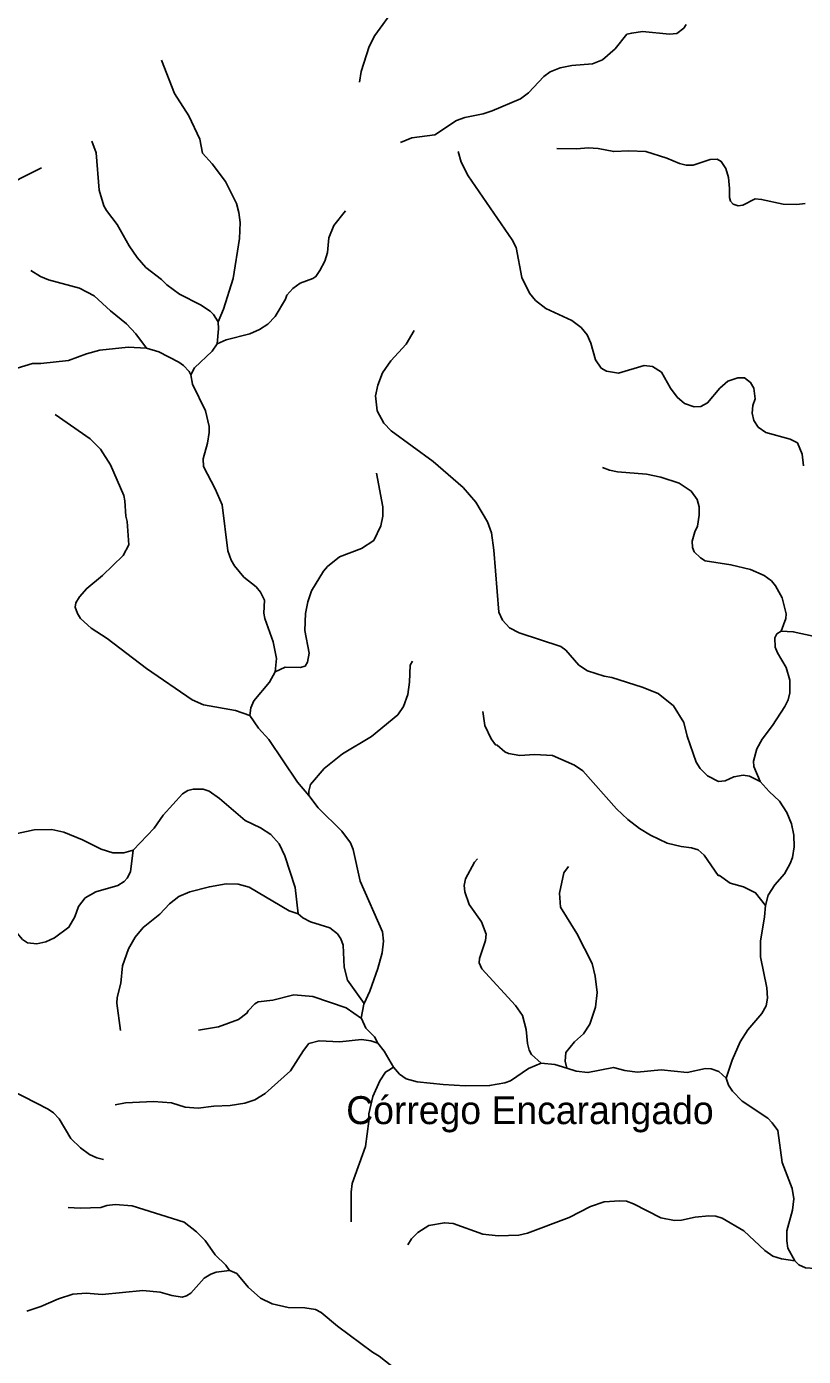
# Model space of a CAD drawing. Extents: x 500 to 555.2, y 9115.7 to 9171.
# Drawn here: x 533.92 to 538.37, y 9135.74 to 9143.36 of the extents above; entities that cross this region are included whole.
import ezdxf
from ezdxf.enums import TextEntityAlignment as Align

# ---------------------------------------------------------------- set-up
doc = ezdxf.new("R2010")
doc.units = 0
doc.header["$LTSCALE"] = 0.064
doc.layers.add('61', color=7, linetype='Continuous')
doc.layers.add('7', color=7, linetype='Continuous', lineweight=25)

msp = doc.modelspace()

# ---------------------------------------------------------------- linework, layer by layer
at = {"layer": '7'}
for points in [[(535.8279, 9143.0382), (535.8385, 9143.0985), (535.8846, 9143.2428), (535.9174, 9143.3044), (536.0326, 9143.4657), (536.1747, 9143.6424), (536.2135, 9143.6797), (536.3104, 9143.7912), (536.3603, 9143.858), (536.4244, 9143.9718), (536.4469, 9144.0394), (536.4599, 9144.1084), (536.4567, 9144.2225), (536.3979, 9144.4686), (536.3929, 9144.563)], [(536.0645, 9142.6919), (536.1293, 9142.719), (536.2598, 9142.7371), (536.3851, 9142.8175), (536.4328, 9142.8351), (536.5381, 9142.8573), (536.5886, 9142.8733), (536.7507, 9142.943), (536.7963, 9142.9767), (536.8854, 9143.0704), (536.9215, 9143.0964), (536.9786, 9143.1202), (537.0447, 9143.1324), (537.164, 9143.1435), (537.2214, 9143.1661), (537.2946, 9143.2288), (537.3612, 9143.3128), (537.3885, 9143.3191), (537.4502, 9143.3275), (537.6059, 9143.3129), (537.6469, 9143.3161), (537.6865, 9143.3469), (537.6996, 9143.3674)], [(534.6945, 9143.164), (534.769, 9142.9733), (534.8515, 9142.8457), (534.9146, 9142.7113), (534.9297, 9142.6322), (534.9848, 9142.5701), (535.0606, 9142.4685), (535.1234, 9142.3429), (535.1379, 9142.2924), (535.1445, 9142.2352), (535.1412, 9142.1432), (535.1051, 9141.9136), (535.0498, 9141.7378), (535.0187, 9141.6649)], [(534.2955, 9142.6996), (534.3198, 9142.6332), (534.3375, 9142.4194), (534.3641, 9142.3304), (534.3789, 9142.3036), (534.4408, 9142.2235), (534.5094, 9142.1007), (534.5546, 9142.0333), (534.6052, 9141.9772), (534.6951, 9141.9086), (534.7252, 9141.8771), (534.798, 9141.8239), (534.9171, 9141.7623), (534.9731, 9141.7269), (534.9924, 9141.7079), (535.0187, 9141.6649)], [(536.3937, 9142.6402), (536.412, 9142.5806), (536.4523, 9142.502), (536.704, 9142.1343), (536.7256, 9142.0907), (536.7591, 9141.9189), (536.8026, 9141.8295), (536.8379, 9141.7869), (536.8964, 9141.7414), (537.0446, 9141.6737), (537.0997, 9141.6331), (537.1331, 9141.5908), (537.155, 9141.5429), (537.1818, 9141.4478), (537.2142, 9141.4007), (537.2445, 9141.3823), (537.3124, 9141.3723), (537.4593, 9141.4162), (537.5071, 9141.4097), (537.5585, 9141.3775), (537.6111, 9141.2852), (537.6497, 9141.234), (537.6903, 9141.1986), (537.7466, 9141.1788), (537.7854, 9141.1805), (537.8228, 9141.2015), (537.8941, 9141.2858), (537.9402, 9141.3265), (537.9966, 9141.3449), (538.0346, 9141.3458), (538.07, 9141.3187), (538.0873, 9141.2863), (538.0954, 9141.2243), (538.0825, 9141.1868), (538.0778, 9141.1423), (538.0873, 9141.1002), (538.1131, 9141.0626), (538.1567, 9141.0325), (538.2959, 9140.9937), (538.3379, 9140.9719), (538.3658, 9140.907), (538.3726, 9140.8415)], [(536.9602, 9142.6582), (537.0748, 9142.6567), (537.1397, 9142.6615), (537.1971, 9142.6579), (537.2855, 9142.6403), (537.3714, 9142.6452), (537.47, 9142.6418), (537.5892, 9142.6022), (537.6622, 9142.5718), (537.7001, 9142.5632), (537.7407, 9142.5635), (537.838, 9142.5959), (537.8787, 9142.5974), (537.9014, 9142.5844), (537.9282, 9142.5428), (537.9429, 9142.493), (537.9494, 9142.4286), (537.9479, 9142.3768), (537.9546, 9142.3557), (537.9703, 9142.3388), (537.9986, 9142.3303), (538.0258, 9142.3344), (538.0968, 9142.3695), (538.1331, 9142.3662), (538.2565, 9142.3386), (538.3345, 9142.3368), (538.3831, 9142.3435)], [(534.0073, 9142.547), (533.8838, 9142.4855), (533.6785, 9142.3649), (533.6038, 9142.3354), (533.5134, 9142.3284), (533.287, 9142.2811), (533.2063, 9142.2924), (533.1083, 9142.3399)], [(535.7481, 9142.3006), (535.681, 9142.2171), (535.6531, 9142.1465), (535.6448, 9142.0618), (535.6301, 9142.0126), (535.6019, 9141.959), (535.5795, 9141.9252), (535.561, 9141.9137), (535.4885, 9141.887), (535.4477, 9141.8559), (535.4126, 9141.8191), (535.4055, 9141.7961), (535.3463, 9141.6955), (535.3027, 9141.6521), (535.2556, 9141.6214), (535.2003, 9141.5977), (535.0646, 9141.5626), (535.0126, 9141.5396)], [(533.9457, 9141.9594), (534.0008, 9141.9254), (534.0477, 9141.9059), (534.2238, 9141.8579), (534.308, 9141.815), (534.4018, 9141.7278), (534.4943, 9141.6535), (534.5471, 9141.5975), (534.6085, 9141.5154)], [(535.0187, 9141.6649), (535.0204, 9141.6247), (535.0126, 9141.5396)], [(536.1426, 9141.6157), (536.0953, 9141.5378), (536.009, 9141.4428), (535.9602, 9141.3733), (535.9337, 9141.3039), (535.9205, 9141.2411), (535.9304, 9141.1568), (535.9688, 9141.0857), (536.011, 9141.0406), (536.2512, 9140.8658), (536.4235, 9140.7165), (536.4945, 9140.6325), (536.5631, 9140.5199), (536.5846, 9140.4576), (536.5979, 9140.358), (536.6276, 9140.0038), (536.6488, 9139.9567), (536.6885, 9139.9138), (536.7442, 9139.884), (536.9816, 9139.8072), (537.0114, 9139.7856), (537.0853, 9139.7005), (537.1348, 9139.6678), (537.2307, 9139.6365), (537.2749, 9139.6298), (537.4475, 9139.5744), (537.5392, 9139.5383), (537.6279, 9139.4662), (537.6868, 9139.3711), (537.7065, 9139.293), (537.7578, 9139.1443), (537.7801, 9139.1084), (537.8226, 9139.066), (537.8861, 9139.0333), (537.9238, 9139.0383), (537.9741, 9139.061), (538.0276, 9139.0692), (538.0642, 9139.0644), (538.125, 9139.0346)], [(535.0126, 9141.5396), (534.9844, 9141.4976), (534.8834, 9141.403), (534.8618, 9141.362)], [(533.6627, 9141.1679), (533.6658, 9141.2013), (533.7145, 9141.2983), (533.7569, 9141.3475), (533.8242, 9141.3869), (533.9543, 9141.4264), (534.0029, 9141.4265), (534.1613, 9141.4446), (534.2637, 9141.4821), (534.3414, 9141.5035), (534.5043, 9141.5199), (534.6085, 9141.5154)], [(534.6085, 9141.5154), (534.6797, 9141.493), (534.7935, 9141.4346), (534.8211, 9141.415), (534.8521, 9141.381), (534.8618, 9141.362)], [(534.8618, 9141.362), (534.8719, 9141.3091), (534.9457, 9141.1564), (534.9667, 9141.0666), (534.9673, 9141.0311), (534.958, 9140.9714), (534.9332, 9140.8817), (534.9346, 9140.8372), (535.0022, 9140.7088), (535.0413, 9140.6171), (535.0738, 9140.3547), (535.0935, 9140.3002), (535.1122, 9140.2678), (535.1664, 9140.204), (535.2359, 9140.1475), (535.2622, 9140.1181), (535.2852, 9140.0713), (535.2809, 9139.9977), (535.2869, 9139.9664), (535.3333, 9139.8331), (535.3539, 9139.7381), (535.3463, 9139.6612)], [(534.0843, 9141.1347), (534.285, 9140.9952), (534.3457, 9140.9361), (534.4021, 9140.8478), (534.4779, 9140.6716), (534.4852, 9140.6401), (534.49, 9140.5528), (534.4982, 9140.5219), (534.5071, 9140.3888), (534.4749, 9140.3271), (534.3572, 9140.2139), (534.2658, 9140.1392), (534.2247, 9140.0917), (534.2032, 9140.0568), (534.1999, 9140.0328), (534.2126, 9139.9951), (534.23, 9139.9663), (534.2911, 9139.9112), (534.3834, 9139.8517), (534.6087, 9139.6807), (534.8696, 9139.502), (534.9353, 9139.4727), (535.1191, 9139.4406), (535.1998, 9139.412)], [(535.9263, 9140.799), (535.9631, 9140.6056), (535.9621, 9140.5529), (535.9518, 9140.4977), (535.9105, 9140.4144), (535.8401, 9140.3686), (535.7138, 9140.3192), (535.6454, 9140.2639), (535.6235, 9140.2372), (535.5544, 9140.1251), (535.5324, 9140.0627), (535.5188, 9139.9959), (535.5153, 9139.8987), (535.5396, 9139.7688), (535.5316, 9139.7179), (535.5169, 9139.6944), (535.4884, 9139.6861), (535.4032, 9139.689), (535.3463, 9139.6612)], [(537.2212, 9140.8311), (537.2606, 9140.8163), (537.3077, 9140.8068), (537.4737, 9140.7932), (537.5563, 9140.7766), (537.6602, 9140.7427), (537.7295, 9140.6964), (537.764, 9140.6474), (537.7755, 9140.6073), (537.7755, 9140.5582), (537.7661, 9140.4951), (537.751, 9140.4635), (537.7358, 9140.4107), (537.7364, 9140.3739), (537.7472, 9140.348), (537.7829, 9140.3134), (537.809, 9140.2968), (537.9566, 9140.2747), (538.07, 9140.2467), (538.148, 9140.2126), (538.1885, 9140.1818), (538.2132, 9140.1539), (538.2512, 9140.0845), (538.2741, 9139.9944), (538.2711, 9139.9664), (538.2453, 9139.8939)], [(538.2453, 9139.8939), (538.2204, 9139.8785), (538.2089, 9139.8572), (538.2108, 9139.8028), (538.2237, 9139.7707), (538.2727, 9139.6855), (538.2953, 9139.6146), (538.2938, 9139.5417), (538.2854, 9139.5017), (538.266, 9139.4631), (538.1954, 9139.3548), (538.1353, 9139.2767), (538.1056, 9139.2209), (538.0861, 9139.1509), (538.0881, 9139.1196), (538.125, 9139.0346)], [(538.4278, 9139.8649), (538.3136, 9139.891), (538.2453, 9139.8939)], [(536.1317, 9139.7222), (536.1199, 9139.6989), (536.1157, 9139.6015), (536.1057, 9139.532), (536.0813, 9139.4636), (536.048, 9139.4154), (535.898, 9139.2918), (535.7323, 9139.1927), (535.6264, 9139.1083), (535.5486, 9139.0172), (535.5383, 9138.9784), (535.5386, 9138.9532)], [(535.3463, 9139.6612), (535.3127, 9139.6015), (535.2237, 9139.496), (535.2065, 9139.4553), (535.1998, 9139.412)], [(535.1998, 9139.412), (535.2501, 9139.3395), (535.3098, 9139.2733), (535.474, 9139.0293), (535.5386, 9138.9532)], [(536.5359, 9139.4345), (536.5472, 9139.3542), (536.5824, 9139.2773), (536.6075, 9139.2437), (536.6173, 9139.2413), (536.6623, 9139.203), (536.6831, 9139.1942), (536.7475, 9139.1826), (536.832, 9139.1889), (536.9353, 9139.1825), (537.0598, 9139.127), (537.1087, 9139.0948), (537.302, 9138.877), (537.3666, 9138.8163), (537.4327, 9138.7654), (537.4962, 9138.7259), (537.5913, 9138.6809), (537.6719, 9138.6607), (537.7302, 9138.6542), (537.7684, 9138.6422), (537.8042, 9138.6123), (537.8832, 9138.4961), (537.8919, 9138.4949), (537.9517, 9138.4516), (538.0282, 9138.4312), (538.0979, 9138.3967), (538.1543, 9138.3243)], [(538.125, 9139.0346), (538.1763, 9138.9761), (538.2348, 9138.9216), (538.2771, 9138.8567), (538.3037, 9138.7905), (538.3183, 9138.7255), (538.3201, 9138.6592), (538.3105, 9138.5984), (538.2968, 9138.5633), (538.2631, 9138.5057), (538.2086, 9138.4427), (538.1705, 9138.3837), (538.1543, 9138.3243)], [(534.5321, 9138.6401), (534.652, 9138.7667), (534.7038, 9138.8401), (534.8141, 9138.9626), (534.8461, 9138.9823), (534.8756, 9138.9889), (534.9331, 9138.989), (534.9673, 9138.979), (535.0268, 9138.9358), (535.1746, 9138.8098), (535.262, 9138.7678), (535.3211, 9138.73), (535.3676, 9138.6773), (535.4015, 9138.6082), (535.4611, 9138.4263), (535.4774, 9138.2769)], [(535.5386, 9138.9532), (535.5924, 9138.8823), (535.7284, 9138.7494), (535.7772, 9138.6827), (535.7934, 9138.6443), (535.8333, 9138.4631), (535.9609, 9138.1731), (535.9662, 9138.1186), (535.9583, 9138.053), (535.9335, 9137.9638), (535.8876, 9137.8325), (535.8553, 9137.7623)], [(533.7538, 9138.7445), (533.7944, 9138.7326), (533.8511, 9138.7326), (533.9642, 9138.7561), (534.0667, 9138.7585), (534.1341, 9138.7445), (534.2418, 9138.7005), (534.348, 9138.6459), (534.4158, 9138.6247), (534.478, 9138.6249), (534.5321, 9138.6401)], [(533.6766, 9138.2922), (533.7562, 9138.2674), (533.7923, 9138.2445), (533.8332, 9138.2055), (533.8985, 9138.1289), (533.9262, 9138.1103), (533.9799, 9138.1033), (534.032, 9138.1157), (534.0805, 9138.1385), (534.1641, 9138.1987), (534.1976, 9138.2594), (534.2179, 9138.318), (534.2569, 9138.3667), (534.3184, 9138.4017), (534.4437, 9138.4384), (534.4803, 9138.4608), (534.4969, 9138.4794), (534.5162, 9138.5166), (534.5321, 9138.6401)], [(536.5052, 9138.591), (536.4873, 9138.5716), (536.4366, 9138.4771), (536.429, 9138.4388), (536.4325, 9138.4022), (536.4563, 9138.3292), (536.5271, 9138.2309), (536.5548, 9138.1586), (536.5506, 9138.1242), (536.5159, 9138.0195), (536.5146, 9137.9947), (536.5302, 9137.9602), (536.722, 9137.751), (536.7625, 9137.6931), (536.7846, 9137.6133), (536.7915, 9137.5327), (536.8008, 9137.4959), (536.8142, 9137.4706), (536.87, 9137.4218)], [(537.0254, 9138.5474), (537, 9138.5106), (536.9753, 9138.3947), (536.9803, 9138.314), (537.075, 9138.1639), (537.1622, 9137.991), (537.1799, 9137.9184), (537.1901, 9137.8251), (537.1818, 9137.7414), (537.1483, 9137.6441), (537.1124, 9137.5894), (537.06, 9137.5434), (537.0114, 9137.4829), (537.0079, 9137.4323), (537.016, 9137.3921)], [(534.4592, 9137.6084), (534.4393, 9137.7636), (534.4409, 9137.7964), (534.4621, 9137.8791), (534.4707, 9137.9781), (534.5046, 9138.0748), (534.5427, 9138.1425), (534.5902, 9138.1983), (534.6843, 9138.2747), (534.7394, 9138.3328), (534.7928, 9138.3761), (534.8559, 9138.4017), (534.9687, 9138.4315), (535.0653, 9138.4476), (535.1329, 9138.4457), (535.197, 9138.4279), (535.4262, 9138.2922), (535.4774, 9138.2769)], [(535.4774, 9138.2769), (535.5042, 9138.2527), (535.5474, 9138.2299), (535.6596, 9138.1949), (535.7022, 9138.162), (535.7212, 9138.1326), (535.7348, 9138.0966), (535.7415, 9137.971), (535.7606, 9137.8957), (535.8553, 9137.7623)], [(538.1543, 9138.3243), (538.1497, 9138.2585), (538.1266, 9138.1186), (538.1266, 9138.0301), (538.1626, 9137.8516), (538.1658, 9137.7926), (538.1596, 9137.75), (538.1334, 9137.7052), (538.0545, 9137.6111), (538.0094, 9137.5425), (537.9642, 9137.4387), (537.9297, 9137.3344)], [(534.9062, 9137.61), (535.0205, 9137.6293), (535.1347, 9137.6702), (535.184, 9137.7069), (535.1909, 9137.7214), (535.2282, 9137.7602), (535.249, 9137.7715), (535.332, 9137.7824), (535.4529, 9137.8128), (535.5606, 9137.8031), (535.7529, 9137.7381), (535.8398, 9137.6768)], [(535.8553, 9137.7623), (535.8538, 9137.7591), (535.8393, 9137.6779), (535.8398, 9137.6768)], [(535.8398, 9137.6768), (535.8644, 9137.6215), (535.9156, 9137.572), (535.9343, 9137.536)], [(534.4294, 9137.1817), (534.489, 9137.1944), (534.6486, 9137.201), (534.7525, 9137.1943), (534.8296, 9137.1699), (534.9042, 9137.1634), (534.9936, 9137.1748), (535.0887, 9137.1787), (535.1715, 9137.1914), (535.2285, 9137.2119), (535.2876, 9137.2477), (535.4331, 9137.3766), (535.5083, 9137.4941), (535.539, 9137.5326), (535.5973, 9137.5488), (535.716, 9137.5439), (535.8394, 9137.5568), (535.8938, 9137.5494), (535.9343, 9137.536)], [(535.9343, 9137.536), (535.9704, 9137.489), (536.0231, 9137.3973)], [(536.0231, 9137.3973), (536.0573, 9137.3582), (536.0968, 9137.3319), (536.1597, 9137.3139), (536.3085, 9137.2979), (536.4337, 9137.2912), (536.5743, 9137.2929), (536.662, 9137.3089), (536.6939, 9137.3199), (536.7966, 9137.3905), (536.87, 9137.4218)], [(536.87, 9137.4218), (536.9488, 9137.4142), (537.016, 9137.3921)], [(535.7811, 9136.5131), (535.781, 9136.6823), (535.7863, 9136.7315), (535.8629, 9136.9436), (535.8825, 9137.0879), (535.8831, 9137.1305), (535.9059, 9137.2294), (535.945, 9137.3191), (535.9786, 9137.3703), (535.9966, 9137.3815), (536.0231, 9137.3973)], [(537.016, 9137.3921), (537.0701, 9137.3743), (537.1379, 9137.3669), (537.2849, 9137.3963), (537.3498, 9137.3797), (537.4206, 9137.37), (537.558, 9137.3832), (537.7061, 9137.3668), (537.811, 9137.3895), (537.8444, 9137.3879), (537.8885, 9137.3723), (537.9297, 9137.3344)], [(537.9297, 9137.3344), (537.9423, 9137.2957), (537.9652, 9137.2606), (538.0205, 9137.2024), (538.168, 9137.1052), (538.1938, 9137.0796), (538.2249, 9137.0352), (538.2497, 9136.8517), (538.307, 9136.704), (538.3168, 9136.645), (538.3102, 9136.5795)], [(534.3621, 9136.8685), (534.3233, 9136.8783), (534.2819, 9136.8975), (534.2299, 9136.9362), (534.1748, 9136.9888), (534.1084, 9137.1018), (534.0755, 9137.1367), (534.0455, 9137.1583), (533.8321, 9137.2661)], [(534.1603, 9136.5949), (534.2278, 9136.591), (534.3473, 9136.5942), (534.3808, 9136.6056), (534.4294, 9136.6121), (534.5266, 9136.604), (534.824, 9136.5106), (534.8952, 9136.4546), (534.9444, 9136.4055), (535.0027, 9136.3242), (535.0621, 9136.2648), (535.0839, 9136.2335)], [(536.1057, 9136.3798), (536.1263, 9136.4142), (536.1632, 9136.4514), (536.2255, 9136.4911), (536.3152, 9136.507), (536.3655, 9136.5021), (536.535, 9136.4421), (536.6229, 9136.4318), (536.7416, 9136.4367), (536.7914, 9136.4482), (537.0309, 9136.5368), (537.1518, 9136.5994), (537.2298, 9136.6265), (537.3195, 9136.6335), (537.3589, 9136.6301), (537.399, 9136.6152), (537.5551, 9136.5354), (537.6339, 9136.5205), (537.6731, 9136.5219), (537.7526, 9136.5383), (537.8313, 9136.5465), (537.8707, 9136.5448), (537.9071, 9136.5328), (538.0314, 9136.4612), (538.1517, 9136.3477), (538.1966, 9136.3158), (538.2463, 9136.3002), (538.3236, 9136.2883)], [(538.3102, 9136.5795), (538.2774, 9136.4607), (538.2774, 9136.4029), (538.2836, 9136.3617), (538.3236, 9136.2883)], [(538.3236, 9136.2883), (538.3463, 9136.2656), (538.3852, 9136.2498), (538.4403, 9136.2454), (538.4939, 9136.2613), (538.6876, 9136.3693), (538.7557, 9136.3792), (538.8253, 9136.3611), (538.9264, 9136.309), (539.0012, 9136.2897), (539.0789, 9136.254)], [(533.9233, 9136.0005), (534.0035, 9136.0285), (534.1041, 9136.0723), (534.1866, 9136.0974), (534.2632, 9136.1035), (534.3552, 9136.0972), (534.5874, 9136.12), (534.6864, 9136.109), (534.7532, 9136.0905), (534.8132, 9136.0809), (534.8378, 9136.088), (534.8627, 9136.104), (534.9391, 9136.1902), (534.9767, 9136.2133), (535.0083, 9136.2249), (535.0839, 9136.2335)], [(535.0839, 9136.2335), (535.0851, 9136.2336), (535.1252, 9136.2162), (535.1917, 9136.1385), (535.2617, 9136.0763), (535.3283, 9136.0431), (535.4208, 9136.0216), (535.5152, 9136.02), (535.5761, 9136.0104), (535.6098, 9135.9941), (535.7033, 9135.9155), (535.9026, 9135.7667), (535.9423, 9135.7424), (536.0407, 9135.6654)]]:
    msp.add_lwpolyline(points, dxfattribs=at)

# ---------------------------------------------------------------- texts
at = {"layer": '61'}
msp.add_text('Córrego Encarangado', height=0.16, dxfattribs=at).set_placement((536.8053, 9137.0719), align=Align.CENTER)

doc.saveas('drawing.dxf')
